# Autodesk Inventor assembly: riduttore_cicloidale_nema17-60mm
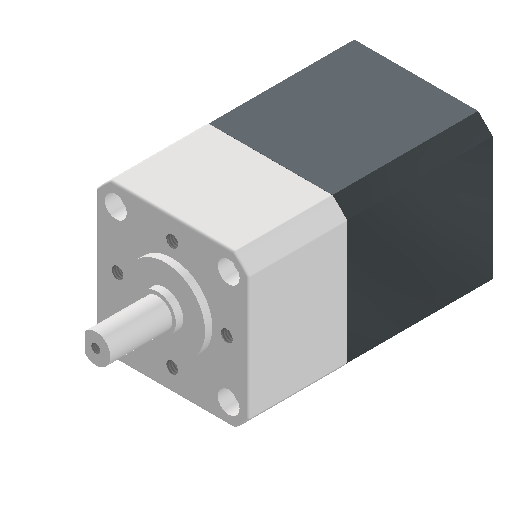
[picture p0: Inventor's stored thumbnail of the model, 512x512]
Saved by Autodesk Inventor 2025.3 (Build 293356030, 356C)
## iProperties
Created: 2026-03
Part Number: riduttore_cicloidale_nema17-60mm
Document SubType Name: Assembly
Designer: R5800u
Author: R5800u
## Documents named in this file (3)
- C:\Users\R5800u\Desktop\robot_riduttore_cicloidale3\Workgroups\NotInProject\riduttore_cicloidale_nema17-60mm.iam
- C:\Users\R5800u\Desktop\robot_riduttore_cicloidale3\Workgroups\NotInProject\NEMA 17.ipt
- C:\Users\R5800u\Desktop\robot_riduttore_cicloidale3\Workgroups\NotInProject\riduttore ciccloidale TS42 15-1.ipt
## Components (2 placed, 2 different names)
1. NEMA 17:1 — Coincidente:1, Coincidente:2, Angolo:1
2. riduttore ciccloidale TS42 15-1:1 — Coincidente:1, Coincidente:2, Angolo:1
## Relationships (3: Mate 2, Angle 1)
- Coincidente:1 [Mate]: NEMA 17:1 ↔ riduttore ciccloidale TS42 15-1:1
- Coincidente:2 [Mate]: NEMA 17:1 ↔ riduttore ciccloidale TS42 15-1:1
- Angolo:1 [Angle]: NEMA 17:1 ↔ riduttore ciccloidale TS42 15-1:1
